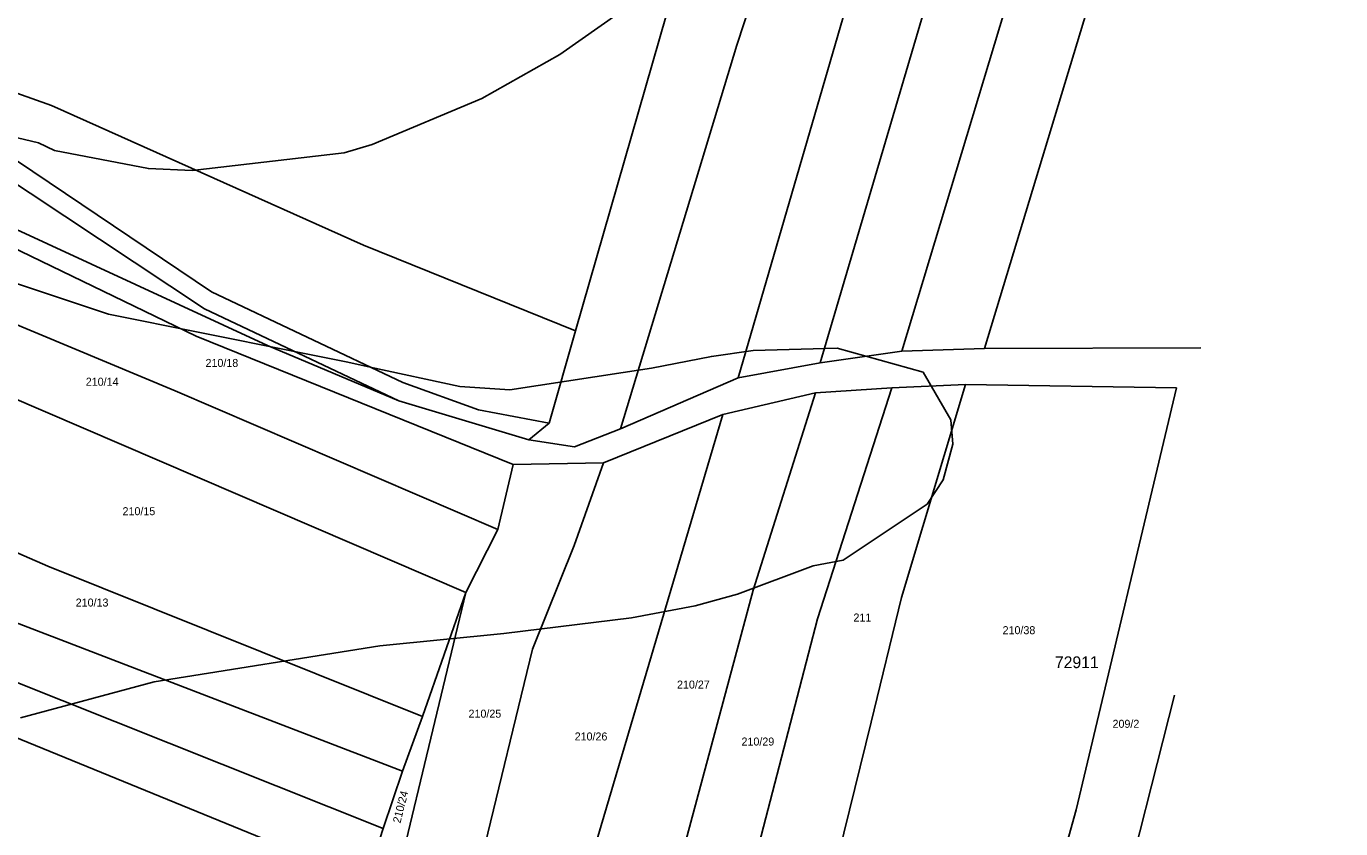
# Model space of a CAD drawing. Extents: x -743888 to -742027, y -1128394 to -1126768.
# Drawn here: x -742743.6 to -742464.3, y -1127789.2 to -1127618.8 of the extents above; entities that cross this region are included whole.
import ezdxf

# ---------------------------------------------------------------- set-up
doc = ezdxf.new("R2010")
doc.units = 0
for name, color, linetype in [('Vrstva 1', 7, 'Continuous'), ('Vrstva 18', 7, 'Continuous'), ('Vrstva 52', 7, 'Continuous'), ('Vrstva 53', 7, 'Continuous'), ('Vrstva 6', 7, 'Continuous')]:
    doc.layers.add(name, color=color, linetype=linetype)

msp = doc.modelspace()

# ---------------------------------------------------------------- linework, layer by layer
at = {"layer": 'Vrstva 1'}
for points in [[(-742626.86, -1127683.46), (-742607.54, -1127616.24)], [(-742756.11, -1127640.29), (-742704.21, -1127675.14)], [(-742757.77, -1127644.27), (-742705.7, -1127678.8)], [(-742704.21, -1127675.14), (-742663.56, -1127694.46)], [(-742705.7, -1127678.8), (-742664.42, -1127698.33)], [(-742632.48, -1127703.04), (-742626.86, -1127683.46)], [(-742663.56, -1127694.46), (-742647.49, -1127700.26)], [(-742664.42, -1127698.33), (-742636.82, -1127706.57)], [(-742647.49, -1127700.26), (-742632.48, -1127703.04)], [(-742636.82, -1127706.57), (-742632.48, -1127703.04)]]:
    msp.add_lwpolyline(points, dxfattribs=at)
at = {"layer": 'Vrstva 52'}
for points in [[(-742760.94, -1127638.75), (-742741, -1127643.5), (-742737.56, -1127645.13), (-742717.63, -1127649), (-742708.31, -1127649.38), (-742676.06, -1127645.63), (-742670.13, -1127643.88), (-742646.81, -1127634.13), (-742630.25, -1127624.75), (-742589.13, -1127595.88), (-742583.19, -1127592.13), (-742551.75, -1127575.13), (-742539.88, -1127569.25), (-742530.56, -1127565.38), (-742514, -1127559.88), (-742491.56, -1127555.63), (-742464.31, -1127550.38)], [(-742777.06, -1127663), (-742726.13, -1127679.88), (-742686.59, -1127687.84), (-742675.25, -1127690.13), (-742670.54, -1127691.14), (-742651.5, -1127695.25), (-742640.88, -1127696), (-742610.75, -1127691.38), (-742598, -1127688.88), (-742589.13, -1127687.63), (-742571.31, -1127687.13), (-742553.06, -1127692.25), (-742547.13, -1127702.38), (-742546.69, -1127707.5), (-742548.81, -1127715.13), (-742552.19, -1127720.25), (-742570, -1127732.13), (-742576.38, -1127733.38), (-742592.5, -1127739.38), (-742601.44, -1127741.88), (-742615, -1127744.38), (-742642.13, -1127747.75), (-742668.44, -1127750.38), (-742716.38, -1127758), (-742744.81, -1127765.63)]]:
    msp.add_lwpolyline(points, dxfattribs=at)
at = {"layer": 'Vrstva 6'}
for points in [[(-742592.59, -1127622.78), (-742562.59, -1127531.26)], [(-742592.33, -1127693.42), (-742553.24, -1127559.15)], [(-742557.53, -1127687.75), (-742527.44, -1127588.04)], [(-742539.98, -1127687.22), (-742509.38, -1127586.29)], [(-742574.91, -1127690.26), (-742552.84, -1127615.42)], [(-742781.53, -1127620.27), (-742738.25, -1127635.58)], [(-742617.34, -1127704.25), (-742592.59, -1127622.78)], [(-742738.25, -1127635.58), (-742671.97, -1127665.27)], [(-742748.4, -1127660.64), (-742692.32, -1127686.56)], [(-742751.48, -1127663.32), (-742707.48, -1127684.6)], [(-742671.97, -1127665.27), (-742626.86, -1127683.46)], [(-742770.35, -1127671.87), (-742711.98, -1127696.17)], [(-742707.48, -1127684.6), (-742640.13, -1127711.82)], [(-742692.32, -1127686.56), (-742664.42, -1127698.33)], [(-742574.91, -1127690.26), (-742557.53, -1127687.75)], [(-742557.53, -1127687.75), (-742539.98, -1127687.22)], [(-742539.98, -1127687.22), (-742494, -1127687.08)], [(-742763.82, -1127690.28), (-742650.2, -1127739.03)], [(-742592.33, -1127693.42), (-742574.91, -1127690.26)], [(-742617.34, -1127704.25), (-742592.33, -1127693.42)], [(-742559.67, -1127695.56), (-742544.01, -1127694.88)], [(-742557.6, -1127740.07), (-742544.01, -1127694.88)], [(-742544.01, -1127694.88), (-742499.23, -1127695.56)], [(-742711.98, -1127696.17), (-742643.36, -1127725.63)], [(-742595.59, -1127701.21), (-742575.9, -1127696.61)], [(-742589.16, -1127738.55), (-742575.9, -1127696.61)], [(-742575.9, -1127696.61), (-742559.67, -1127695.56)], [(-742575.45, -1127744.63), (-742559.67, -1127695.56)], [(-742520.53, -1127785.2), (-742499.23, -1127695.56)], [(-742625.54, -1127802.36), (-742595.59, -1127701.21)], [(-742620.93, -1127711.51), (-742595.59, -1127701.21)], [(-742627.13, -1127708.08), (-742617.34, -1127704.25)], [(-742636.82, -1127706.57), (-742627.13, -1127708.08)], [(-742643.36, -1127725.63), (-742640.13, -1127711.82)], [(-742640.13, -1127711.82), (-742620.93, -1127711.51)], [(-742627.15, -1127729.06), (-742620.93, -1127711.51)], [(-742786.49, -1127712.73), (-742739.02, -1127733.43)], [(-742650.2, -1127739.03), (-742643.36, -1127725.63)], [(-742792.35, -1127727.57), (-742663.65, -1127776.96)], [(-742636.01, -1127751.08), (-742627.15, -1127729.06)], [(-742739.02, -1127733.43), (-742659.43, -1127765.34)], [(-742793.05, -1127739.22), (-742667.79, -1127789.16)], [(-742664.19, -1127797.36), (-742650.2, -1127739.03)], [(-742659.43, -1127765.34), (-742650.2, -1127739.03)], [(-742608.79, -1127811.54), (-742589.16, -1127738.55)], [(-742564.08, -1127766.54), (-742557.6, -1127740.07)], [(-742592.67, -1127810.85), (-742575.45, -1127744.63)], [(-742786.9, -1127753.03), (-742691.75, -1127791.9)], [(-742646.74, -1127795.08), (-742636.01, -1127751.08)], [(-742511.87, -1127809.1), (-742499.62, -1127760.84)], [(-742663.65, -1127776.96), (-742659.43, -1127765.34)], [(-742571.03, -1127794.76), (-742564.08, -1127766.54)], [(-742667.79, -1127789.16), (-742663.65, -1127776.96)], [(-742527.52, -1127810.4), (-742520.53, -1127785.2)], [(-742668.48, -1127791.31), (-742667.79, -1127789.16)]]:
    msp.add_lwpolyline(points, dxfattribs=at)

# ---------------------------------------------------------------- texts
at = {"layer": 'Vrstva 18'}
for s, p in [('210/18', (-742705.5, -1127691.12)), ('210/14', (-742730.94, -1127695.11)), ('210/15', (-742723.13, -1127722.61)), ('210/13', (-742733.08, -1127742.01)), ('211', (-742567.83, -1127745.19)), ('210/38', (-742536.15, -1127747.88)), ('210/27', (-742605.32, -1127759.43)), ('210/25', (-742649.62, -1127765.61)), ('209/2', (-742512.79, -1127767.76)), ('210/26', (-742627.07, -1127770.45)), ('210/29', (-742591.62, -1127771.53))]:
    msp.add_text(s, height=1.7, dxfattribs=at).set_placement(p)
msp.add_text('210/24', height=1.7, rotation=75.8299, dxfattribs=at).set_placement((-742664.1, -1127788.14))
at = {"layer": 'Vrstva 53'}
msp.add_text('72911', height=2.5, dxfattribs=at).set_placement((-742525.03, -1127755.09))

doc.saveas('drawing.dxf')
